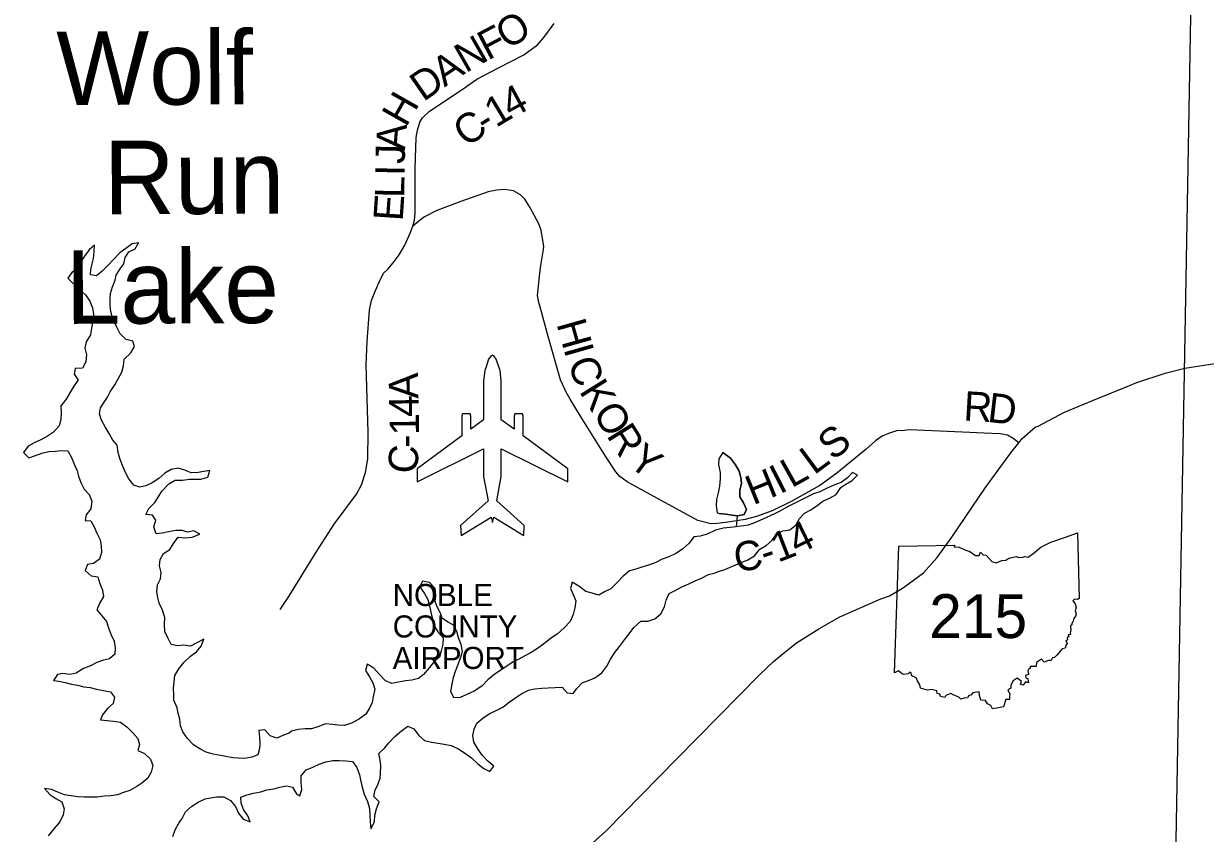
# Model space of a CAD drawing. Extents: x -452339 to 6403467, y -1 to 1814750.
# Drawn here: x -369125 to -357078, y 1612095 to 1620353 of the extents above; entities that cross this region are included whole.
import ezdxf

# ---------------------------------------------------------------- set-up
doc = ezdxf.new("R2010")
doc.units = 0
for name, color, linetype in [('Default', 7, 'Continuous'), ('GM_X_Adjacent_County_Text', 7, 'Continuous'), ('GM_X_County', 7, 'Continuous'), ('GM_X_Major_River', 7, 'Continuous'), ('GM_X_Minor_Lake_Text', 7, 'Continuous'), ('GM_X_Section_Text', 7, 'Continuous')]:
    doc.layers.add(name, color=color, linetype=linetype)

msp = doc.modelspace()

# ---------------------------------------------------------------- linework, layer by layer
at = {"layer": 'Default'}
msp.add_line((-360245, 1613733), (-360203, 1615024), dxfattribs=at)
for points in [[(-365157, 1618288), (-365139, 1618350), (-365133, 1618423), (-365132, 1618877), (-365122, 1619190), (-365110, 1619266), (-365084, 1619348), (-365058, 1619393), (-364986, 1619461), (-364655, 1619682), (-364503, 1619788), (-364285, 1619901), (-364027, 1620035), (-363887, 1620136), (-363820, 1620210), (-363716, 1620354)], [(-359552, 1616186), (-360093, 1616210), (-360149, 1616204), (-360225, 1616200), (-360309, 1616174), (-360373, 1616145), (-360441, 1616099), (-360536, 1616015), (-360834, 1615768), (-361008, 1615644), (-361294, 1615483), (-361494, 1615385), (-361653, 1615328), (-361769, 1615296), (-361967, 1615264), (-362053, 1615254), (-362119, 1615253), (-362253, 1615285), (-362731, 1615549), (-362973, 1615679), (-363047, 1615733), (-363087, 1615781), (-363194, 1615943), (-363446, 1616349), (-363552, 1616524), (-363594, 1616596), (-363652, 1616722), (-363779, 1617162), (-363857, 1617451), (-363873, 1617509), (-363887, 1617579), (-363861, 1617807), (-363851, 1617888), (-363827, 1618028), (-363823, 1618080), (-363850, 1618246), (-363872, 1618312), (-363964, 1618482), (-364014, 1618563), (-364060, 1618607), (-364132, 1618647), (-364222, 1618660), (-364300, 1618656), (-364388, 1618638), (-364666, 1618540), (-364913, 1618447), (-365039, 1618381), (-365097, 1618339), (-365157, 1618288)], [(-366510, 1614377), (-366421, 1614510), (-366142, 1614963), (-365958, 1615248), (-365732, 1615555), (-365680, 1615651), (-365641, 1615777), (-365617, 1615914), (-365613, 1616188), (-365632, 1616873), (-365622, 1617112), (-365598, 1617432), (-365578, 1617528), (-365538, 1617633), (-365499, 1617717), (-365457, 1617807), (-365413, 1617849), (-365359, 1617915), (-365295, 1617996), (-365239, 1618094), (-365183, 1618216), (-365157, 1618288)], [(-358980, 1616078), (-359037, 1616123), (-359093, 1616155), (-359169, 1616171), (-359333, 1616177), (-359552, 1616186), (-359552, 1616186)], [(-361995, 1615980), (-362036, 1615914), (-362042, 1615854), (-362023, 1615774), (-362024, 1615710), (-362031, 1615635), (-362045, 1615567), (-362060, 1615501), (-362065, 1615435), (-362055, 1615365), (-362035, 1615357)], [(-362035, 1615357), (-361966, 1615352), (-361900, 1615342), (-361848, 1615335), (-361780, 1615346), (-361755, 1615398), (-361786, 1615466), (-361822, 1615529), (-361825, 1615598), (-361808, 1615662), (-361814, 1615724), (-361831, 1615788), (-361868, 1615853), (-361920, 1615923), (-361995, 1615980)], [(-361995, 1615980), (-361920, 1615923), (-361868, 1615853), (-361831, 1615788), (-361814, 1615724), (-361808, 1615662), (-361825, 1615598), (-361822, 1615529), (-361786, 1615466), (-361755, 1615398), (-361780, 1615346), (-361848, 1615335)], [(-362144, 1614737), (-362084, 1614750), (-362032, 1614768), (-361975, 1614787), (-361905, 1614816), (-361817, 1614855), (-361742, 1614884), (-361674, 1614926), (-361619, 1614993), (-361555, 1615030), (-361498, 1615082), (-361447, 1615147), (-361385, 1615182), (-361315, 1615191), (-361254, 1615239), (-361216, 1615306), (-361163, 1615362), (-361099, 1615395), (-361036, 1615438), (-360976, 1615483), (-360909, 1615513), (-360843, 1615552), (-360794, 1615623), (-360742, 1615655), (-360678, 1615694), (-360623, 1615747), (-360675, 1615776), (-360727, 1615722), (-360792, 1615673), (-360864, 1615646), (-360934, 1615615), (-361009, 1615580), (-361073, 1615558), (-361147, 1615521), (-361214, 1615486), (-361284, 1615453), (-361343, 1615421), (-361417, 1615380), (-361469, 1615353), (-361550, 1615316), (-361620, 1615285), (-361674, 1615263), (-361739, 1615240), (-361809, 1615227), (-361861, 1615223), (-361921, 1615214), (-361989, 1615209), (-362073, 1615188), (-362156, 1615147), (-362228, 1615127), (-362292, 1615118), (-362341, 1615055), (-362407, 1614993), (-362476, 1614948), (-362546, 1614917), (-362616, 1614890), (-362679, 1614859), (-362743, 1614835), (-362813, 1614812), (-362882, 1614791), (-362948, 1614772), (-363012, 1614720), (-363075, 1614655), (-363140, 1614590), (-363202, 1614559), (-363260, 1614523), (-363330, 1614546), (-363394, 1614563), (-363464, 1614615), (-363533, 1614656), (-363550, 1614594), (-363524, 1614532), (-363495, 1614466), (-363504, 1614396), (-363521, 1614326), (-363553, 1614257), (-363614, 1614191), (-363685, 1614128), (-363753, 1614083), (-363824, 1614026), (-363876, 1613987), (-363949, 1613941), (-364009, 1613908), (-364077, 1613871), (-364128, 1613849), (-364186, 1613812), (-364259, 1613761), (-364317, 1613724), (-364392, 1613660), (-364454, 1613597), (-364531, 1613544), (-364605, 1613511), (-364674, 1613482), (-364738, 1613476), (-364771, 1613543), (-364756, 1613616), (-364742, 1613684), (-364723, 1613750), (-364698, 1613810), (-364672, 1613881), (-364649, 1613951)], [(-361848, 1615335), (-361900, 1615342), (-361966, 1615352), (-362035, 1615357)], [(-361861, 1615223), (-361854, 1615250), (-361849, 1615296), (-361848, 1615335)], [(-360203, 1615024), (-359631, 1615033), (-359640, 1615017), (-359586, 1615014), (-359529, 1614986), (-359480, 1614969), (-359421, 1614928), (-359385, 1614928), (-359370, 1614962), (-359343, 1614936), (-359311, 1614931), (-359255, 1614869), (-359209, 1614856), (-359153, 1614877), (-359113, 1614881), (-359082, 1614902), (-359004, 1614919), (-358982, 1614909), (-358940, 1614911), (-358919, 1614919), (-358883, 1614912), (-358819, 1614959), (-358754, 1615014), (-358652, 1615066), (-358502, 1615116), (-358382, 1615160), (-358365, 1614490)], [(-358365, 1614490), (-358382, 1614481), (-358410, 1614485), (-358428, 1614466), (-358405, 1614435), (-358394, 1614402), (-358404, 1614365), (-358394, 1614335), (-358401, 1614310), (-358418, 1614285), (-358424, 1614261), (-358439, 1614236), (-358438, 1614222), (-358452, 1614211), (-358449, 1614169), (-358456, 1614145), (-358454, 1614125), (-358477, 1614120), (-358471, 1614104), (-358486, 1614091), (-358482, 1614069), (-358499, 1614055), (-358483, 1614027), (-358496, 1614018), (-358506, 1613983), (-358536, 1613976), (-358593, 1613914), (-358614, 1613890), (-358637, 1613885), (-358650, 1613860), (-358678, 1613860), (-358722, 1613843), (-358749, 1613872), (-358798, 1613837), (-358804, 1613797), (-358865, 1613798), (-358863, 1613778), (-358876, 1613772), (-358889, 1613752), (-358882, 1613716), (-358911, 1613706), (-358907, 1613685), (-358888, 1613673), (-358880, 1613632), (-358911, 1613640), (-358936, 1613606), (-358962, 1613614), (-358953, 1613643), (-358997, 1613678), (-359038, 1613650), (-359060, 1613606), (-359060, 1613576), (-359091, 1613558), (-359071, 1613516), (-359075, 1613487), (-359074, 1613460), (-359113, 1613461), (-359136, 1613387)], [(-359136, 1613387), (-359203, 1613372), (-359249, 1613364), (-359265, 1613398), (-359298, 1613416), (-359320, 1613449), (-359368, 1613454), (-359379, 1613501), (-359384, 1613538), (-359449, 1613529), (-359467, 1613506), (-359490, 1613500), (-359504, 1613476), (-359535, 1613474), (-359569, 1613463), (-359591, 1613486), (-359647, 1613509), (-359672, 1613521), (-359724, 1613503), (-359735, 1613481), (-359776, 1613490), (-359786, 1613515), (-359811, 1613522), (-359816, 1613548), (-359870, 1613562), (-359911, 1613556), (-359983, 1613577), (-359988, 1613610), (-360012, 1613652), (-360025, 1613680), (-360070, 1613702), (-360080, 1613736), (-360094, 1613735), (-360108, 1613721), (-360159, 1613715), (-360179, 1613729), (-360207, 1613753), (-360245, 1613733)]]:
    msp.add_lwpolyline(points, dxfattribs=at)
msp.add_lwpolyline([(-364658, 1616149), (-365114, 1615812), (-365114, 1615682), (-364435, 1616017), (-364435, 1615735), (-364390, 1615485), (-364670, 1615235), (-364665, 1615132), (-364359, 1615321), (-364345, 1615266), (-364331, 1615321), (-364025, 1615132), (-364021, 1615235), (-364300, 1615485), (-364255, 1615735), (-364255, 1616017), (-363576, 1615682), (-363576, 1615812), (-364032, 1616149), (-364032, 1616350), (-364040, 1616375), (-364117, 1616375), (-364124, 1616350), (-364124, 1616217), (-364255, 1616314), (-364255, 1616314), (-364255, 1616711), (-364268, 1616817), (-364279, 1616854), (-364306, 1616931), (-364331, 1616965), (-364345, 1616971), (-364359, 1616965), (-364384, 1616931), (-364411, 1616854), (-364422, 1616817), (-364435, 1616711), (-364435, 1616314), (-364566, 1616217), (-364566, 1616350), (-364573, 1616375), (-364651, 1616375), (-364658, 1616350)], close=True, dxfattribs=at)
at = {"layer": 'GM_X_Major_River'}
msp.add_lwpolyline([(-363750, 1611615), (-363191, 1612119), (-362466, 1612857), (-361618, 1613715), (-361480, 1613848), (-361402, 1613914), (-361245, 1614037), (-361019, 1614181), (-360805, 1614304), (-360385, 1614487), (-360297, 1614517), (-360165, 1614595), (-360105, 1614640), (-360003, 1614715), (-359951, 1614754), (-359810, 1614908), (-359662, 1615116), (-359320, 1615623), (-359059, 1615977), (-358980, 1616078), (-358945, 1616123), (-358809, 1616240), (-358789, 1616245), (-358515, 1616391), (-358177, 1616530), (-357874, 1616654), (-357777, 1616694), (-357487, 1616787), (-357288, 1616839), (-356410, 1616977)], dxfattribs=at)
at = {"layer": 'GM_X_Minor_Lake_Text'}
for points in [[(-367951, 1618116), (-368019, 1618106), (-368082, 1618061), (-368144, 1618016), (-368209, 1617947), (-368267, 1617887), (-368324, 1617830), (-368383, 1617781), (-368444, 1617791), (-368438, 1617841), (-368429, 1617891), (-368411, 1617959), (-368406, 1618027), (-368403, 1618093), (-368456, 1618045), (-368504, 1617980), (-368543, 1617926), (-368570, 1617857), (-368634, 1617814), (-368673, 1617758), (-368554, 1617641), (-368493, 1617586), (-368449, 1617522), (-368424, 1617454), (-368411, 1617386), (-368419, 1617318), (-368432, 1617246), (-368443, 1617178), (-368487, 1617109), (-368500, 1617045), (-368485, 1616975), (-368492, 1616905), (-368526, 1616838), (-368598, 1616836), (-368609, 1616779), (-368570, 1616720), (-368612, 1616655), (-368655, 1616589), (-368692, 1616524), (-368746, 1616456), (-368741, 1616384), (-368746, 1616315), (-368764, 1616251), (-368821, 1616188), (-368880, 1616146), (-368948, 1616107), (-369016, 1616078), (-369079, 1616043), (-369125, 1615979), (-369072, 1615925), (-369004, 1615950), (-368939, 1615971), (-368869, 1615988), (-368801, 1615992), (-368741, 1616001), (-368673, 1615996), (-368638, 1615928), (-368610, 1615862), (-368579, 1615793), (-368564, 1615737), (-368540, 1615673), (-368509, 1615607), (-368458, 1615550), (-368428, 1615482), (-368439, 1615406), (-368488, 1615343), (-368498, 1615285), (-368438, 1615283), (-368407, 1615220), (-368378, 1615156), (-368346, 1615088), (-368333, 1615026), (-368330, 1614958), (-368350, 1614892), (-368411, 1614849), (-368473, 1614837), (-368496, 1614776), (-368436, 1614723), (-368368, 1614712), (-368347, 1614644), (-368322, 1614576), (-368312, 1614510), (-368347, 1614448), (-368380, 1614375), (-368328, 1614314), (-368279, 1614256), (-368260, 1614190), (-368236, 1614126), (-368201, 1614057), (-368192, 1613987), (-368196, 1613923), (-368249, 1613876), (-368309, 1613861), (-368377, 1613837), (-368442, 1613804), (-368514, 1613777), (-368588, 1613730), (-368651, 1613715), (-368730, 1613725), (-368781, 1613716), (-368821, 1613656)], [(-367684, 1614297), (-367690, 1614307), (-367710, 1614370), (-367743, 1614444), (-367758, 1614500), (-367768, 1614560), (-367759, 1614630), (-367728, 1614691), (-367722, 1614757), (-367739, 1614823), (-367734, 1614889), (-367698, 1614949), (-367635, 1614990), (-367598, 1615050), (-367548, 1615115), (-367478, 1615108), (-367408, 1615116), (-367329, 1615145), (-367389, 1615179), (-367455, 1615166), (-367505, 1615185), (-367573, 1615183), (-367647, 1615172), (-367713, 1615157), (-367775, 1615151), (-367799, 1615222), (-367778, 1615289), (-367812, 1615342), (-367880, 1615346), (-367847, 1615410), (-367788, 1615471), (-367754, 1615523), (-367713, 1615588), (-367644, 1615659), (-367580, 1615697), (-367506, 1615698), (-367434, 1615709), (-367370, 1615706), (-367318, 1615708), (-367247, 1615727), (-367225, 1615797), (-367287, 1615787), (-367347, 1615776), (-367417, 1615773), (-367483, 1615798), (-367548, 1615820), (-367621, 1615807), (-367685, 1615768), (-367748, 1615713), (-367814, 1615671), (-367878, 1615638), (-367941, 1615625), (-368002, 1615645), (-368052, 1615710), (-368085, 1615774), (-368118, 1615846), (-368144, 1615919), (-368161, 1615981), (-368170, 1616053), (-368214, 1616105), (-368253, 1616173), (-368294, 1616242), (-368330, 1616308), (-368351, 1616374), (-368340, 1616436), (-368304, 1616492), (-368271, 1616545), (-368241, 1616597), (-368194, 1616670), (-368159, 1616738), (-368125, 1616799), (-368108, 1616863), (-368101, 1616931), (-368033, 1616996), (-367996, 1617060), (-368013, 1617114), (-368079, 1617132), (-368139, 1617189), (-368176, 1617257), (-368205, 1617323), (-368225, 1617376), (-368240, 1617440), (-368243, 1617492), (-368241, 1617544), (-368238, 1617601), (-368218, 1617669), (-368193, 1617737), (-368180, 1617789), (-368142, 1617854), (-368103, 1617904), (-368088, 1617967), (-368052, 1618025), (-367988, 1618056), (-367957, 1618110), (-367951, 1618116)], [(-362144, 1614737), (-362084, 1614750), (-362032, 1614768), (-361975, 1614787), (-361905, 1614816), (-361817, 1614855), (-361742, 1614884), (-361674, 1614926), (-361619, 1614993), (-361555, 1615030), (-361498, 1615082), (-361447, 1615147), (-361385, 1615182), (-361315, 1615191), (-361254, 1615239), (-361216, 1615306), (-361163, 1615362), (-361099, 1615395), (-361036, 1615438), (-360976, 1615483), (-360909, 1615513), (-360843, 1615552), (-360794, 1615623), (-360742, 1615655), (-360678, 1615694), (-360623, 1615747), (-360675, 1615776), (-360727, 1615722), (-360792, 1615673), (-360864, 1615646), (-360934, 1615615), (-361009, 1615580), (-361073, 1615558), (-361147, 1615521), (-361214, 1615486), (-361284, 1615453), (-361343, 1615421), (-361417, 1615380), (-361469, 1615353), (-361550, 1615316), (-361620, 1615285), (-361674, 1615263), (-361739, 1615240), (-361809, 1615227), (-361861, 1615223)], [(-361861, 1615223), (-361921, 1615214), (-361989, 1615209), (-362073, 1615188), (-362156, 1615147), (-362228, 1615127), (-362292, 1615118), (-362341, 1615055), (-362407, 1614993), (-362476, 1614948), (-362546, 1614917), (-362616, 1614890), (-362679, 1614859), (-362743, 1614835), (-362813, 1614812), (-362882, 1614791), (-362948, 1614772), (-363012, 1614720), (-363075, 1614655), (-363140, 1614590), (-363202, 1614559), (-363260, 1614523), (-363330, 1614546), (-363394, 1614563), (-363464, 1614615), (-363533, 1614656), (-363550, 1614594), (-363524, 1614532), (-363495, 1614466), (-363504, 1614396), (-363521, 1614326), (-363553, 1614257), (-363614, 1614191), (-363685, 1614128), (-363753, 1614083), (-363824, 1614026), (-363876, 1613987), (-363949, 1613941), (-364009, 1613908), (-364077, 1613871), (-364128, 1613849), (-364186, 1613812), (-364259, 1613761), (-364317, 1613724), (-364392, 1613660), (-364454, 1613597), (-364531, 1613544), (-364605, 1613511), (-364674, 1613482), (-364738, 1613476), (-364771, 1613543), (-364756, 1613616), (-364742, 1613684), (-364723, 1613750), (-364698, 1613810), (-364672, 1613881), (-364649, 1613951)], [(-366344, 1612499), (-366309, 1612478), (-366290, 1612544), (-366295, 1612612), (-366296, 1612682), (-366246, 1612743), (-366182, 1612767), (-366113, 1612802), (-366043, 1612825), (-365973, 1612838), (-365909, 1612838), (-365841, 1612835), (-365771, 1612828), (-365729, 1612766), (-365702, 1612692), (-365687, 1612626), (-365673, 1612565), (-365652, 1612495), (-365619, 1612421), (-365598, 1612349), (-365594, 1612283), (-365591, 1612211), (-365586, 1612143), (-365547, 1612212), (-365546, 1612280), (-365526, 1612344), (-365499, 1612416), (-365554, 1612472), (-365542, 1612538), (-365515, 1612590), (-365490, 1612659), (-365486, 1612711), (-365483, 1612783), (-365491, 1612843), (-365502, 1612911), (-365441, 1612969), (-365403, 1613020), (-365340, 1613085), (-365271, 1613142), (-365209, 1613190), (-365147, 1613161), (-365096, 1613095), (-365038, 1613044), (-364966, 1613025), (-364899, 1613017), (-364837, 1613004), (-364767, 1612993), (-364697, 1612960), (-364631, 1612916), (-364560, 1612865), (-364495, 1612806), (-364433, 1612758), (-364373, 1612725), (-364331, 1612781), (-364394, 1612833), (-364450, 1612892), (-364495, 1612956), (-364534, 1613025), (-364544, 1613093), (-364533, 1613158), (-364504, 1613220), (-364440, 1613273), (-364371, 1613319), (-364307, 1613350), (-364239, 1613383), (-364176, 1613434), (-364108, 1613482), (-364047, 1613523), (-363977, 1613556), (-363913, 1613569), (-363842, 1613577), (-363776, 1613580), (-363706, 1613583), (-363634, 1613586), (-363585, 1613528), (-363523, 1613523), (-363484, 1613573), (-363430, 1613632), (-363365, 1613655), (-363303, 1613681), (-363229, 1613732), (-363178, 1613799), (-363141, 1613871), (-363096, 1613940), (-363050, 1614002), (-362999, 1614069), (-362950, 1614130), (-362904, 1614196), (-362833, 1614259), (-362761, 1614260), (-362689, 1614283), (-362630, 1614333), (-362593, 1614404), (-362575, 1614472), (-362544, 1614541), (-362482, 1614573), (-362413, 1614608), (-362343, 1614639), (-362279, 1614672), (-362214, 1614698), (-362144, 1614737)], [(-364649, 1613951), (-364664, 1614023), (-364691, 1614089), (-364709, 1614153), (-364744, 1614218), (-364804, 1614254), (-364857, 1614289), (-364875, 1614341), (-364910, 1614405), (-364928, 1614459), (-364921, 1614519), (-364928, 1614591), (-364986, 1614654), (-365058, 1614667), (-365086, 1614609), (-365037, 1614542), (-365004, 1614480), (-364986, 1614416), (-364973, 1614350), (-364958, 1614280), (-364940, 1614212), (-364901, 1614151), (-364849, 1614091), (-364852, 1614025), (-364869, 1613957), (-364884, 1613894), (-364936, 1613850), (-364989, 1613783), (-365049, 1613714), (-365100, 1613676), (-365166, 1613657), (-365232, 1613652), (-365302, 1613636), (-365370, 1613625), (-365436, 1613650), (-365496, 1613714), (-365553, 1613779), (-365621, 1613820), (-365639, 1613758), (-365598, 1613693), (-365564, 1613629), (-365545, 1613565), (-365560, 1613491), (-365573, 1613429), (-365595, 1613378), (-365636, 1613310), (-365712, 1613255), (-365783, 1613218), (-365855, 1613197), (-365923, 1613198), (-365975, 1613204), (-366047, 1613211), (-366125, 1613182), (-366189, 1613160), (-366254, 1613161), (-366326, 1613156), (-366394, 1613137)], [(-366394, 1613137), (-366416, 1613117), (-366476, 1613098), (-366545, 1613066), (-366610, 1613089), (-366666, 1613152), (-366726, 1613146), (-366721, 1613078), (-366717, 1613012), (-366720, 1612962), (-366736, 1612897), (-366799, 1612871), (-366871, 1612860), (-366939, 1612861), (-366993, 1612865), (-367065, 1612880), (-367119, 1612891), (-367194, 1612904), (-367264, 1612922), (-367328, 1612959), (-367392, 1613000), (-367453, 1613064), (-367502, 1613131), (-367526, 1613191), (-367533, 1613259), (-367548, 1613321), (-367558, 1613375), (-367593, 1613455), (-367594, 1613509), (-367596, 1613577), (-367591, 1613641), (-367582, 1613705), (-367542, 1613774), (-367487, 1613840), (-367424, 1613901), (-367362, 1613946), (-367315, 1614006), (-367286, 1614075), (-367353, 1614042), (-367423, 1614005), (-367493, 1614016), (-367557, 1614008), (-367621, 1614023), (-367654, 1614091), (-367686, 1614154), (-367687, 1614224), (-367684, 1614297)], [(-368821, 1613656), (-368767, 1613648), (-368701, 1613633), (-368636, 1613617), (-368576, 1613606), (-368512, 1613591), (-368446, 1613584), (-368382, 1613566), (-368312, 1613551), (-368240, 1613538), (-368197, 1613486), (-368213, 1613420), (-368268, 1613369), (-368319, 1613305), (-368341, 1613254), (-368273, 1613247), (-368209, 1613238), (-368137, 1613229), (-368074, 1613181), (-368012, 1613120), (-367959, 1613062), (-367944, 1613002), (-367962, 1612940), (-367891, 1612911), (-367831, 1612853), (-367808, 1612786), (-367823, 1612719), (-367859, 1612657), (-367920, 1612606), (-367972, 1612572), (-368043, 1612533), (-368105, 1612512), (-368169, 1612487), (-368235, 1612477), (-368305, 1612474), (-368375, 1612463), (-368433, 1612463), (-368503, 1612466), (-368571, 1612469), (-368639, 1612478), (-368707, 1612490), (-368775, 1612517), (-368839, 1612542), (-368911, 1612553), (-368859, 1612492), (-368796, 1612451), (-368734, 1612417), (-368711, 1612345), (-368721, 1612285), (-368754, 1612213), (-368815, 1612144), (-368876, 1612069)], [(-367603, 1612065), (-367579, 1612131), (-367544, 1612198), (-367509, 1612248), (-367473, 1612315), (-367410, 1612374), (-367346, 1612412), (-367273, 1612447), (-367221, 1612458), (-367155, 1612468), (-367085, 1612467), (-367015, 1612430), (-366964, 1612368), (-366933, 1612303), (-366885, 1612239), (-366815, 1612214), (-366839, 1612276), (-366884, 1612339), (-366908, 1612403), (-366911, 1612463), (-366847, 1612488), (-366780, 1612505), (-366708, 1612519), (-366644, 1612538), (-366574, 1612551), (-366512, 1612567), (-366446, 1612580), (-366384, 1612567), (-366344, 1612499)]]:
    msp.add_lwpolyline(points, dxfattribs=at)
at = {"layer": 'GM_X_Section_Text'}
msp.add_line((-357093, 1628200), (-357520, 1603979), dxfattribs=at)

# ---------------------------------------------------------------- texts
at = {"layer": 'Default'}
for s, p in [('NOBLE', (-365362, 1614414)), ('COUNTY', (-365362, 1614093)), ('AIRPORT', (-365362, 1613772))]:
    msp.add_text(s, height=225, rotation=0, dxfattribs=at).set_placement(p)
msp.add_text('215', height=447.7, dxfattribs=at).set_placement((-359893, 1614087))
at = {"layer": 'GM_X_Adjacent_County_Text'}
for s, p in [('Wolf', (-368790, 1619522)), ('Run', (-368306, 1618408)), ('Lake', (-368695, 1617291))]:
    msp.add_text(s, height=750, rotation=0.2496, dxfattribs=at).set_placement(p)
at = {"layer": 'GM_X_County'}
for s, rotation, p in [('F', 27.6382, (-364393, 1619974)), ('O', 32.4395, (-364189, 1620082)), ('N', 29.7336, (-364619, 1619845)), ('A', 33.7143, (-364834, 1619701)), ('D', 34.7974, (-365050, 1619551)), ('H', 60.4932, (-365226, 1619288)), ('1', 30.9468, (-364310, 1619288)), ('4', 28.1013, (-364155, 1619381)), ('C', 33.7788, (-364615, 1619086)), ('-', 33.2614, (-364411, 1619222)), ('A', 85.5001, (-365237, 1619057)), ('J', 88.9276, (-365239, 1618921)), ('L', 89.0684, (-365245, 1618574)), ('I', 89.0008, (-365241, 1618798)), ('E', 86.1745, (-365261, 1618334)), ('H', 285.7638, (-363694, 1617293)), ('I', 285.8691, (-363622, 1617038)), ('C', 289.8281, (-363581, 1616898)), ('A', 91.1547, (-365099, 1616529)), ('K', 302.0071, (-363467, 1616604)), ('R', 356.6963, (-359548, 1616306)), ('4', 91.0325, (-365096, 1616343)), ('O', 301.4386, (-363328, 1616381)), ('D', 353.3223, (-359307, 1616293)), ('1', 90.6734, (-365093, 1616157)), ('R', 302.0772, (-363188, 1616153)), ('S', 39.5448, (-360871, 1615889)), ('-', 89.7324, (-365094, 1616028)), ('C', 85.1586, (-365116, 1615756)), ('Y', 323.1999, (-362976, 1615855)), ('L', 36.4778, (-361066, 1615745)), ('L', 29.2122, (-361296, 1615613)), ('H', 21.984, (-361688, 1615440)), ('I', 27.132, (-361417, 1615551)), ('4', 25.8309, (-361238, 1614932)), ('1', 21.1367, (-361435, 1614855)), ('C', 9.5162, (-361858, 1614756)), ('-', 18.9463, (-361563, 1614810))]:
    msp.add_text(s, height=300, rotation=rotation, dxfattribs=at).set_placement(p)

doc.saveas('drawing.dxf')
